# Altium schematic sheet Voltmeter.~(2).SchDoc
size A4
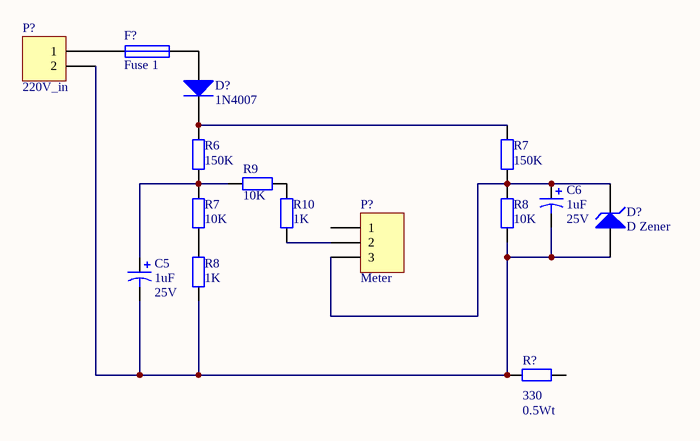
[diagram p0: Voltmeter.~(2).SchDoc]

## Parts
(Parts that share a designator on the sheet are numbered #1, #2 ... from top to bottom, then left to right.)
C5  25V  value 1uF  [RB7.6-15]
C6  25V  value 1uF  [RB7.6-15]
D?#1  1N4007  [DO-41]
D?#2  D Zener  [DIODE-0.7]
F?  Fuse 1  [PIN-W2/E2.8]
P?#1  220V_in  [HDR1X2]
P?#2  Meter  [HDR1X3]
R6  value 150K  [AXIAL-0.4]  (hidden comment: Res2)
R7#1  value 150K  [AXIAL-0.4]  (hidden comment: Res2)
R7#2  value 10K  [AXIAL-0.4]  (hidden comment: Res2)
R8#1  value 10K  [AXIAL-0.4]  (hidden comment: Res2)
R8#2  value 1K  [AXIAL-0.4]  (hidden comment: Res2)
R9  value 10K  [AXIAL-0.4]  (hidden comment: Res2)
R10  value 1K  [AXIAL-0.4]  (hidden comment: Res2)
R?  0.5Wt  value 330  [AXIAL-0.4]

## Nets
NetC5_1: C5.1 R6.1 R7#2.2 R9.2
NetC5_2: C5.2 C6.2 D?#2.1(A) P?#1.2 R8#1.1 R8#2.1 R?.1
NetC6_1: C6.1 D?#2.2(K) P?#2.3 R7#1.1 R8#1.2
NetD?#1_1: D?#1.1(A) F?.2
NetD?#1_2: D?#1.2(K) R6.2 R7#1.2
NetF?_1: F?.1 P?#1.1
NetP?#2_2: P?#2.2 R10.2
NetR7#2_1: R7#2.1 R8#2.2
NetR9_1: R9.1 R10.1

Not connected (* = marked no-connect by the designer): P?#2 1; R? 2

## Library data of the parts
C5 C6 = Cap Pol1: Polarized Capacitor (Radial)
D?#1 = Diode 1N4007: 1 Amp General Purpose Rectifier
D?#2 = D Zener: Zener Diode
F? = Fuse 1: Fuse
P?#1 = Header 2: Header, 2-Pin
P?#2 = Header 3: Header, 3-Pin
R6 R7#1 R7#2 R8#1 R8#2 R9 R10 R? = Res2: Resistor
